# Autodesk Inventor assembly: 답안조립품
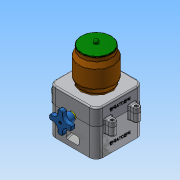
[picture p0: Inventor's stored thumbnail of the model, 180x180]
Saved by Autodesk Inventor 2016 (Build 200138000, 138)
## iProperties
Created: 2018-01
Part Number: 답안조립품
Material: 일반
Document SubType Name: Assembly
Designer: Administrator
Author: Administrator
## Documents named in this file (9)
- C:\Users\Administrator\Desktop\480107V1022\답안조립품.iam
- C:\Users\Administrator\Desktop\480107V1022\본체.ipt
- C:\Users\Administrator\Desktop\480107V1022\본체커버.ipt
- C:\Users\Administrator\Desktop\480107V1022\핸들축.ipt
- C:\Users\Administrator\Desktop\480107V1022\핸들.ipt
- C:\Users\Administrator\Desktop\480107V1022\볼트 M3x12.ipt
- C:\Users\Administrator\Desktop\480107V1022\볼트 M4x12.ipt
- C:\Users\Administrator\Desktop\480107V1022\용기.ipt
- C:\Users\Administrator\Desktop\480107V1022\용기캡.ipt
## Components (2 placed, 2 different names)
1. 핸들축:1
2. 핸들:1
